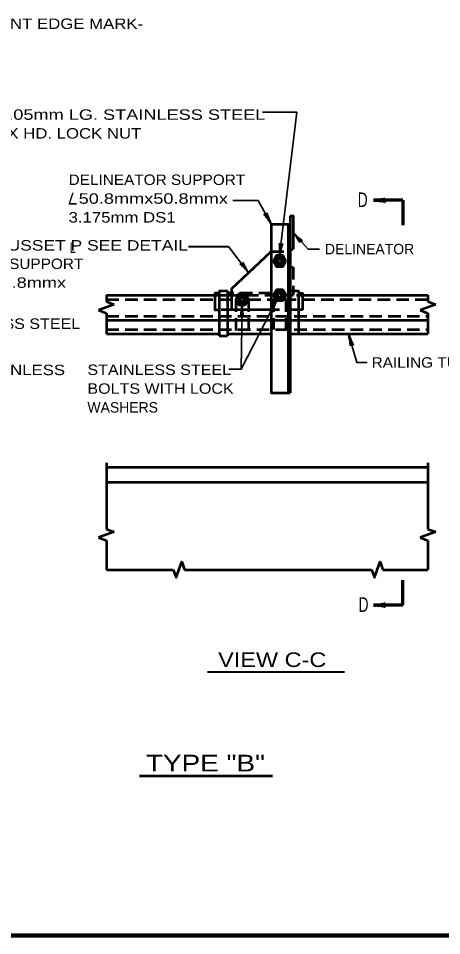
# Model space of a CAD drawing. Extents: x -105 to 751, y -65 to 479.
# Drawn here: x 186.6 to 308.2, y -53.4 to 210.2 of the extents above; entities that cross this region are included whole.
import ezdxf

# ---------------------------------------------------------------- set-up
doc = ezdxf.new("R2010")
doc.units = 0
doc.header["$LTSCALE"] = 1.2
doc.linetypes.add('MEDIUM_DASHED', pattern=[4.5, 3, -1.5])
doc.layers.add('1', color=7, linetype='Continuous', lineweight=35)

msp = doc.modelspace()

# ---------------------------------------------------------------- linework, layer by layer
at = {"layer": '1'}
for p, q in [((256.721, 183.285), (266.596, 183.285)), ((261.661, 142.048), (266.596, 183.285)), ((201.022, 156.957), (203.288, 156.957)), ((252.747, 137.089), (246.957, 144.68)), ((250.617, 109.431), (247.071, 109.431))]:
    msp.add_line(p, q, dxfattribs=at)
at = {"layer": '1', "lineweight": 70}
for p, q in [((297.061, 157.96), (288.661, 157.96)), ((297.061, 157.96), (297.061, 150.76)), ((297.061, 41.56), (297.061, 48.76)), ((297.061, 41.56), (288.661, 41.56))]:
    msp.add_line(p, q, dxfattribs=at)
at = {"layer": '1', "lineweight": 53}
for p, q in [((264.661, 153.448), (264.661, 102.582)), ((259.261, 151.048), (264.661, 151.048)), ((264.061, 151.048), (264.061, 102.582)), ((247.861, 132.468), (259.261, 143.248)), ((264.661, 143.848), (265.561, 143.848)), ((261.47, 138.905), (259.865, 140.509)), ((261.726, 138.905), (259.959, 140.672)), ((261.983, 138.905), (260.053, 140.835)), ((261.213, 138.905), (260.125, 139.992)), ((262.24, 138.905), (260.147, 140.998)), ((261.184, 140.217), (260.241, 141.16)), ((261.12, 140.537), (260.335, 141.323)), ((261.182, 140.732), (260.429, 141.486)), ((261.295, 140.877), (260.523, 141.649)), ((261.451, 140.977), (260.617, 141.811)), ((261.664, 141.021), (260.711, 141.974)), ((263.106, 139.835), (260.893, 142.048)), ((263.2, 139.998), (261.15, 142.048)), ((262.497, 138.905), (261.403, 139.998)), ((263.294, 140.161), (261.406, 142.048)), ((263.388, 140.323), (261.663, 142.048)), ((262.636, 139.022), (261.722, 139.936)), ((262.73, 139.184), (261.917, 139.997)), ((263.454, 140.513), (261.92, 142.048)), ((262.824, 139.347), (262.061, 140.11)), ((262.918, 139.51), (262.161, 140.266)), ((263.104, 141.121), (262.177, 142.048)), ((263.012, 139.673), (262.205, 140.48)), ((262.753, 141.728), (262.433, 142.048)), ((260.957, 138.905), (260.476, 139.385)), ((244.261, 131.868), (244.261, 118.968)), ((244.261, 131.868), (246.661, 131.868)), ((246.661, 131.868), (246.661, 118.968)), ((247.861, 132.468), (247.861, 126.468)), ((261.31, 131.068), (260.538, 131.84)), ((261.466, 131.168), (260.632, 132.002)), ((261.679, 131.212), (260.726, 132.165)), ((263.121, 130.026), (260.908, 132.239)), ((263.215, 130.189), (261.165, 132.239)), ((263.309, 130.352), (261.422, 132.239)), ((263.403, 130.515), (261.678, 132.239)), ((263.47, 130.704), (261.935, 132.239)), ((263.119, 131.312), (262.192, 132.239)), ((262.768, 131.919), (262.448, 132.239)), ((211.861, 130.668), (211.861, 128.824)), ((211.861, 130.668), (247.861, 130.668)), ((250.685, 127.896), (249.08, 129.501)), ((250.942, 127.896), (249.174, 129.663)), ((251.198, 127.896), (249.268, 129.826)), ((251.455, 127.896), (249.362, 129.989)), ((250.399, 129.209), (249.456, 130.151)), ((250.335, 129.529), (249.55, 130.314)), ((250.397, 129.723), (249.644, 130.477)), ((250.51, 129.868), (249.738, 130.64)), ((250.666, 129.968), (249.832, 130.802)), ((250.879, 130.012), (249.926, 130.965)), ((252.321, 128.827), (250.108, 131.039)), ((252.415, 128.989), (250.365, 131.039)), ((252.509, 129.152), (250.622, 131.039)), ((252.603, 129.315), (250.878, 131.039)), ((252.669, 129.505), (251.135, 131.039)), ((252.133, 128.501), (251.376, 129.257)), ((252.319, 130.112), (251.392, 131.039)), ((252.227, 128.664), (251.42, 129.471)), ((251.968, 130.719), (251.648, 131.039)), ((261.485, 129.096), (259.88, 130.701)), ((261.742, 129.096), (259.974, 130.863)), ((261.998, 129.096), (260.068, 131.026)), ((261.228, 129.096), (260.14, 130.184)), ((262.255, 129.096), (260.162, 131.189)), ((261.199, 130.409), (260.256, 131.352)), ((261.135, 130.729), (260.35, 131.514)), ((261.197, 130.923), (260.444, 131.677)), ((260.971, 129.096), (260.491, 129.576)), ((262.512, 129.096), (261.418, 130.189)), ((262.651, 129.213), (261.737, 130.127)), ((262.745, 129.376), (261.932, 130.189)), ((262.839, 129.538), (262.076, 130.301)), ((262.933, 129.701), (262.176, 130.458)), ((263.027, 129.864), (262.22, 130.671)), ((263.491, 130.668), (265.561, 130.668)), ((266.467, 130.668), (304.261, 130.668)), ((304.261, 130.668), (304.261, 128.824)), ((214.116, 128.003), (209.606, 126.362)), ((211.861, 128.824), (214.116, 128.003)), ((250.428, 127.896), (249.34, 128.983)), ((250.172, 127.896), (249.691, 128.376)), ((251.712, 127.896), (250.618, 128.989)), ((251.851, 128.013), (250.937, 128.927)), ((251.945, 128.176), (251.132, 128.989)), ((252.039, 128.338), (251.276, 129.101)), ((306.516, 128.003), (302.006, 126.362)), ((304.261, 128.824), (306.516, 128.003)), ((209.606, 126.362), (211.861, 125.541)), ((211.861, 125.541), (211.861, 119.568)), ((259.261, 126.468), (244.861, 126.468)), ((268.261, 126.468), (267.061, 126.468)), ((302.006, 126.362), (304.261, 125.541)), ((304.261, 125.541), (304.261, 119.568)), ((211.861, 123.468), (304.261, 123.468)), ((211.861, 119.568), (244.261, 119.568)), ((244.261, 118.968), (246.661, 118.968)), ((246.661, 119.568), (259.261, 119.568)), ((264.661, 119.568), (304.261, 119.568)), ((211.861, 82.476), (211.861, 63.443)), ((304.261, 82.476), (304.261, 63.443)), ((211.861, 81.276), (304.261, 81.276)), ((211.861, 76.96), (304.261, 76.96)), ((211.861, 63.443), (214.116, 62.622)), ((304.261, 63.443), (306.516, 62.622)), ((214.116, 62.622), (209.606, 60.981)), ((209.606, 60.981), (211.861, 60.16)), ((306.516, 62.622), (302.006, 60.981)), ((302.006, 60.981), (304.261, 60.16)), ((211.861, 60.16), (211.861, 51.76)), ((304.261, 60.16), (304.261, 51.76)), ((211.861, 51.76), (231.061, 51.76)), ((234.344, 51.76), (288.061, 51.76)), ((291.344, 51.76), (304.261, 51.76)), ((221.389, -7.428), (259.612, -7.428))]:
    msp.add_line(p, q, dxfattribs=at)
at = {"layer": '1', "lineweight": 40}
for p, q in [((235.496, 144.68), (246.957, 144.68)), ((240.913, 22.402), (280.324, 22.402))]:
    msp.add_line(p, q, dxfattribs=at)
at = {"layer": '1', "linetype": 'MEDIUM_DASHED', "lineweight": 53}
for p, q in [((259.261, 143.248), (264.061, 143.248)), ((211.861, 129.468), (249.061, 129.468)), ((259.261, 131.268), (246.661, 131.268)), ((247.861, 130.668), (249.754, 130.668)), ((249.061, 129.468), (249.061, 119.568)), ((251.998, 130.668), (259.861, 130.668)), ((252.661, 129.468), (252.661, 119.568)), ((252.661, 129.468), (260.554, 129.468)), ((259.861, 129.468), (259.861, 120.768)), ((262.798, 129.468), (304.261, 129.468)), ((263.461, 129.468), (263.461, 120.768)), ((211.861, 124.668), (304.261, 124.668)), ((267.061, 126.468), (259.261, 126.468)), ((211.861, 120.768), (304.261, 120.768))]:
    msp.add_line(p, q, dxfattribs=at)
at = {"layer": '1', "lineweight": 158}
msp.add_line((744.128, -53.4), (-47.472, -53.4), dxfattribs=at)
at = {"layer": '1'}
for points in [[(259.261, 151.048), (255.458, 157.828), (248.236, 157.828)], [(265.561, 148.648), (269.808, 143.861), (273.146, 143.861)], [(250.876, 127.896), (250.617, 109.431), (260.768, 129.096)], [(281.449, 119.568), (283.888, 111.309), (286.809, 111.309)]]:
    msp.add_lwpolyline(points, dxfattribs=at)
at = {"layer": '1', "lineweight": 53}
for points in [[(264.661, 153.448), (265.561, 153.448), (265.561, 143.848)], [(259.261, 151.048), (259.261, 102.582), (264.661, 102.582)], [(264.661, 131.868), (267.061, 131.868), (267.061, 119.568)], [(244.261, 131.268), (243.061, 131.268), (243.061, 126.468), (244.261, 126.468)], [(267.061, 131.268), (268.261, 131.268), (268.261, 126.468)], [(231.061, 51.76), (231.882, 49.505), (233.523, 54.015), (234.344, 51.76)], [(288.061, 51.76), (288.882, 49.505), (290.523, 54.015), (291.344, 51.76)]]:
    msp.add_lwpolyline(points, dxfattribs=at)
for points in [[(263.476, 140.476), (262.568, 142.048), (260.753, 142.048), (259.846, 140.476), (260.753, 138.905), (262.568, 138.905)], [(263.491, 130.668), (262.583, 132.239), (260.768, 132.239), (259.861, 130.668), (260.768, 129.096), (262.583, 129.096)], [(252.691, 129.468), (251.783, 131.039), (249.968, 131.039), (249.061, 129.468), (249.968, 127.896), (251.783, 127.896)]]:
    msp.add_lwpolyline(points, close=True, dxfattribs=at)
at = {"layer": '1', "linetype": 'MEDIUM_DASHED', "lineweight": 53}
msp.add_lwpolyline([(264.661, 138.748), (265.561, 138.748), (265.561, 130.668)], dxfattribs=at)
at = {"layer": '1', "lineweight": 53}
for centre in [(261.661, 140.476), (250.876, 129.467), (261.676, 130.667)]:
    msp.add_circle(centre, 0.544, dxfattribs=at)
at = {"layer": '1', "lineweight": 70}
for centre, major_axis, ratio, start_param, end_param in [((289.963, 158.287), (-2.145, -0.165), 0.122415, 0.8963533, 3.1415927), ((289.992, 157.702), (-2.105, 0.233), 0.07063, 3.1407148, 5.41811), ((289.992, 41.818), (-2.105, -0.233), 0.07063, 0.8650754, 3.1424706), ((289.963, 41.232), (-2.145, 0.165), 0.122415, 3.1415927, 5.386832)]:
    msp.add_ellipse(centre, major_axis=major_axis, ratio=ratio, start_param=start_param, end_param=end_param, dxfattribs=at)
at = {"layer": '1', "lineweight": 40}
for centre, major_axis, ratio, start_param, end_param in [((258.331, 152.028), (1.212, -1.777), 0.122415, 0.8963533, 3.1415927), ((258.331, 152.028), (1.212, -1.777), 0.122415, 0.8963533, 3.1415927), ((258.825, 152.345), (0.847, -1.941), 0.07063, 3.1407148, 5.41811), ((258.825, 152.345), (0.847, -1.941), 0.07063, 3.1407148, 5.41811), ((266.263, 147.474), (-1.241, 1.717), 0.07063, 3.1407148, 5.41811), ((266.678, 147.889), (-1.562, 1.479), 0.122415, 0.8963533, 3.1415927), ((261.487, 143.388), (-0.069, -2.15), 0.122415, 0.8963533, 3.1415927), ((261.487, 143.388), (-0.069, -2.15), 0.122415, 0.8963533, 3.1415927), ((262.073, 143.353), (-0.46, -2.068), 0.07063, 3.1407148, 5.41811), ((262.073, 143.353), (-0.46, -2.068), 0.07063, 3.1407148, 5.41811), ((252.134, 138.312), (1.111, -1.804), 0.07063, 3.1407148, 5.41811), ((251.69, 137.929), (1.449, -1.59), 0.122415, 0.8963533, 3.1415927), ((250.603, 126.555), (0.24, 2.105), 0.07063, 3.1407148, 5.41811), ((250.603, 126.555), (0.24, 2.105), 0.07063, 3.1407148, 5.41811), ((251.189, 126.582), (-0.157, 2.145), 0.122415, 0.8963533, 3.1415927), ((251.189, 126.582), (-0.157, 2.145), 0.122415, 0.8963533, 3.1415927), ((259.926, 128.017), (1.154, 1.776), 0.07063, 3.1407148, 5.41811), ((260.462, 127.78), (0.816, 1.99), 0.122415, 0.8963533, 3.1415927), ((281.587, 118.206), (0.395, -2.081), 0.07063, 6.2823074, 8.5597026), ((281.587, 118.206), (0.395, -2.081), 0.07063, 6.2823074, 8.5597026), ((282.138, 118.406), (-0.787, 2.002), 0.122415, 0.8963533, 3.1415927), ((282.138, 118.406), (-0.787, 2.002), 0.122415, 0.8963533, 3.1415927)]:
    msp.add_ellipse(centre, major_axis=major_axis, ratio=ratio, start_param=start_param, end_param=end_param, dxfattribs=at)

# ---------------------------------------------------------------- texts
at = {"layer": '1'}
for s, height, width, p in [('ICATED BY THE PAVEMENT EDGE MARK-', 3, 1.2, (126.397, 207.177)), ('7.94mm 0 x 19.05mm LG. STAINLESS STEEL', 3, 1.3, (149.16, 181.065)), ('BOLT WITH HEX HD. LOCK NUT', 3, 1.2, (149.16, 175.665)), ('DELINEATOR SUPPORT', 3, 1.1, (200.998, 162.338)), ('/ 50.8mmx50.8mmx', 3, 1.3, (200.998, 156.938)), ('D', 4.2, 0.7, (284.103, 155.977)), ('3.175mm DS1', 3, 1.2, (200.998, 151.538)), ('4.76mm GUSSET P SEE DETAIL', 3, 1.25, (160.054, 143.482)), ('L', 3, 0.75, (201.331, 142.833)), ('DELINEATOR SUPPORT', 3, 1.1, (154.479, 138.184)), ('/ 50.8mmx50.8mmx', 3, 1.3, (154.479, 132.784)), ('STAINLESS STEEL', 3, 1.15, (163.056, 120.964)), ('19.05mm STAINLESS', 3, 1.2, (152.091, 107.679)), ('STAINLESS STEEL', 3, 1.15, (206.412, 107.728)), ('RAILING TUBE', 3, 1.1, (288.087, 109.833)), ('BOLTS WITH LOCK', 3, 1.15, (206.412, 102.328)), ('D', 4.2, 0.7, (284.359, 39.658)), ('VIEW C-C', 4.2, 1.2, (243.98, 23.808)), ('TYPE "B"', 4.8, 1.25, (223.218, -6.208))]:
    msp.add_text(s, height=height, dxfattribs=dict(at, width=width)).set_placement(p)
for s, p in [('DELINEATOR', (274.687, 142.412)), ('WASHERS', (206.412, 96.928))]:
    msp.add_text(s, height=3, dxfattribs=at).set_placement(p)

doc.saveas('drawing.dxf')
